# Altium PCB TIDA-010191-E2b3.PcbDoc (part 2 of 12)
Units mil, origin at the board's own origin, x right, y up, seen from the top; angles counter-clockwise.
Board outline 9842.52 x 9842.4 mil, 6 copper layers (Layer 1 - Top Layer, Layer 2 - GND Layer, Layer 3 - Signal, Layer 4 - Signal, Layer 5 - GND, Bottom Layer), stack 59.9 mil thick; 1178 components, 642 nets, 3329 pads, 2967 vias.
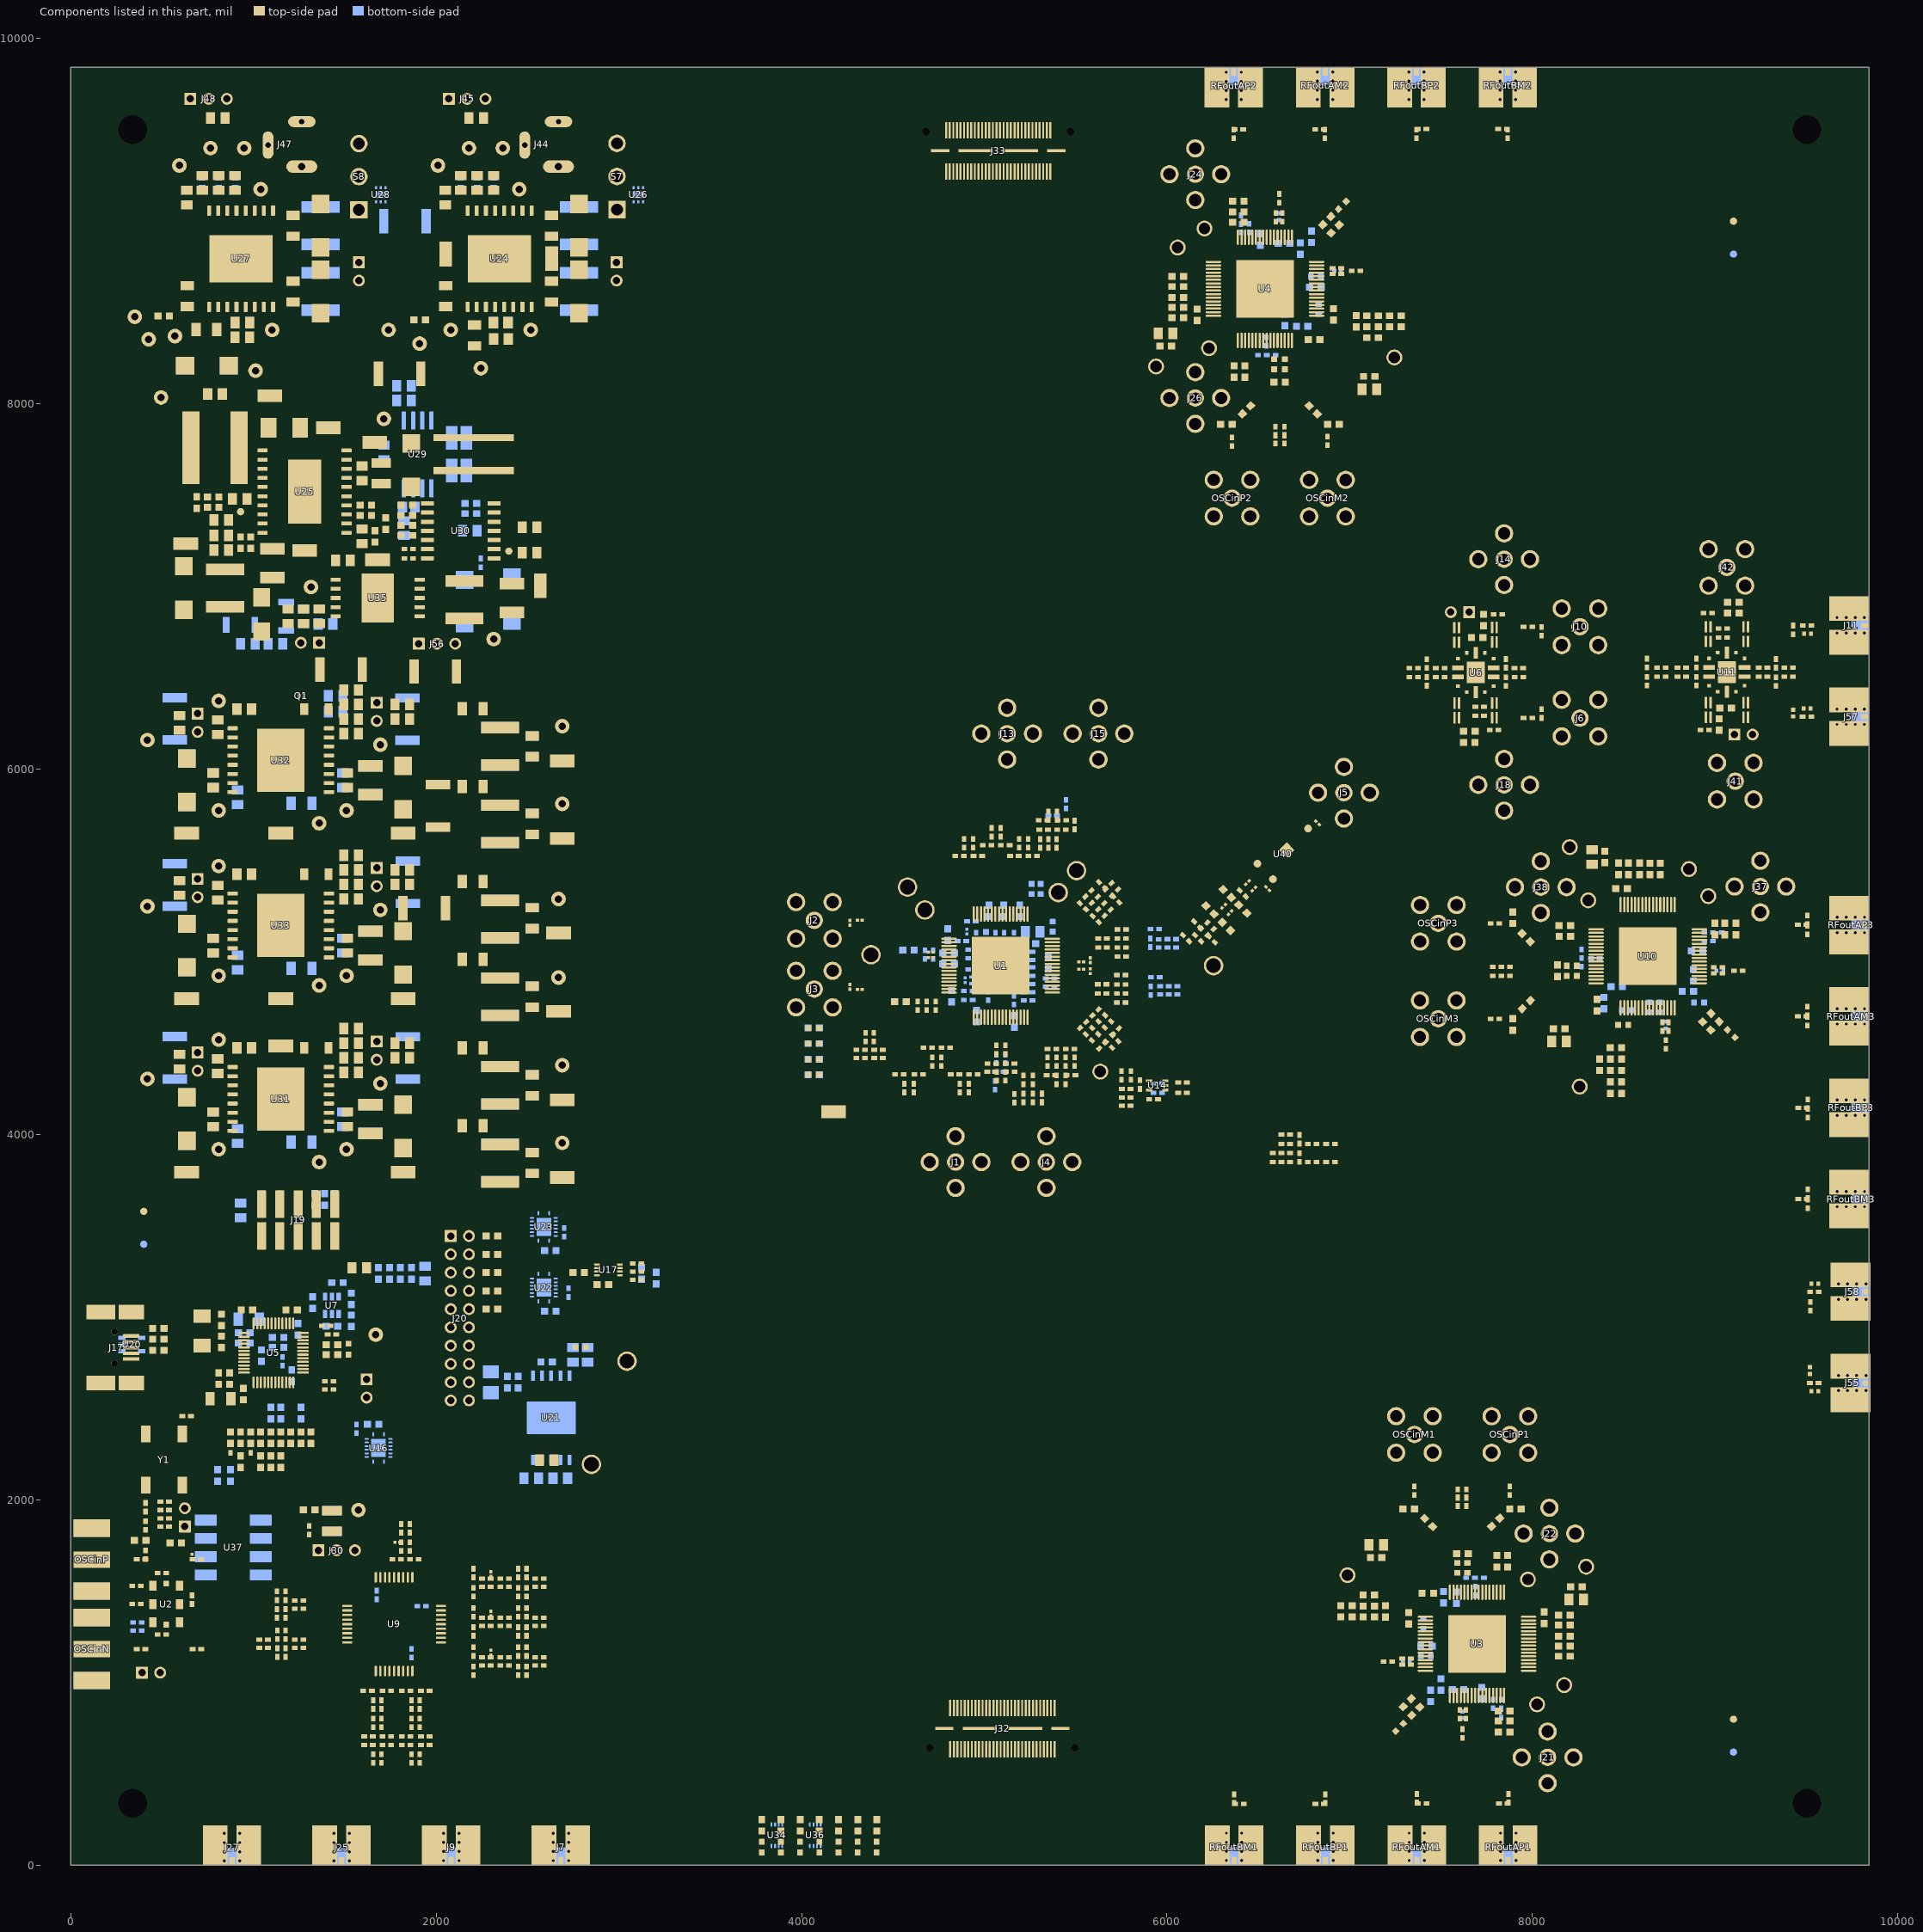
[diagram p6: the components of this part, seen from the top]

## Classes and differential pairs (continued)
net class C230_Nets: GND P3V8
net class C229_Nets: NetC229_1 VSENSE
net class C228_Nets: GND VIN_P5V0
net class C227_Nets: GND VIN_P5V0
net class C226_Nets: GND NetC226_2
net class C225_Nets: NetC223_1 P5V0
net class C224_Nets: NetC223_1 P5V0
net class C223_Nets: NetC223_1 VIN_P5V0
net class C222_Nets: GND VREGIN
net class C221_Nets: GND VREGIN
net class C220_Nets: GND VREGIN
net class C219_Nets: GND VREGIN
net class C218_Nets: GND VREGIN
net class C217_Nets: NetC217_1 NetC217_2
net class C213_Nets: GND NetC213_1
net class C212_Nets: GND NetC212_1
net class C211_Nets: GND NetC210_1
net class C210_Nets: GND NetC210_1
net class C209_Nets: GND NetC208_2
net class C208_Nets: GND NetC208_2
net class C207_Nets: NetC206_1 NetC207_2
net class C206_Nets: GND NetC206_1
net class C205_Nets: GND NetC203_1
net class C204_Nets: LMX3_RFoutA3_N NetC204_1
net class C203_Nets: NetC203_1 NetC203_2
net class C202_Nets: LMX3_RFoutA3_P NetC202_1
net class C201_Nets: GND P4V5
net class C200_Nets: GND P4V5
net class C199_Nets: GND VREGIN
net class C198_Nets: GND P4V5
net class C197_Nets: GND P4V5
net class C196_Nets: GND VREGIN
net class C195_Nets: LMX2_OSCin- NetC195_1
net class C194_Nets: LMX_OSCin3- NetC194_1
net class C193_Nets: LMX_OSCin3+ NetC193_1
net class C192_Nets: ADC_SYSREF2- RFoutB2_P
net class C191_Nets: LMX2_OSCin+ NetC191_1
net class C190_Nets: GND NetC190_1
net class C189_Nets: GND NetC189_2
net class C188_Nets: GND NetC187_2
net class C187_Nets: GND NetC187_2
net class C186_Nets: CPout1 GND
net class C185_Nets: GND SYNC
net class C184_Nets: GND RESET
net class C183_Nets: GND NetC183_1
net class C182_Nets: GND NetC182_1
net class C181_Nets: ADC_SYSREF3- RFoutB3_P
net class C180_Nets: GND NetC180_1
net class C175_Nets: GND NetC172_1
net class C174_Nets: GND NetC174_1
net class C173_Nets: GND NetC173_2
net class C172_Nets: NetC172_1 NetC172_2
net class C171_Nets: GND NetC171_1
net class C170_Nets: GND NetC170_2
net class C169_Nets: GND NetC169_2
net class C168_Nets: GND NetC168_1
net class C167_Nets: GND NetC167_2
net class C166_Nets: ADC_SYSREF3+ RFoutB3_N
net class C165_Nets: GND NetC165_2
net class C164_Nets: GND NetC164_2
net class C163_Nets: GND P3V3_LMX
net class C162_Nets: GND P3V3_LMX
net class C161_Nets: GND P3V3_LMX
net class C160_Nets: GND P3V3_LMX
net class C159_Nets: GND NetC159_1
net class C158_Nets: ADC_CLK3- RFoutA3_N
net class C157_Nets: GND NetC157_2
net class C156_Nets: GND NetC156_2
net class C155_Nets: GND NetC155_2
net class C154_Nets: GND NetC154_2
net class C153_Nets: ADC_CLK3+ RFoutA3_P
net class C152_Nets: GND NetC152_1
net class C151_Nets: GND NetC151_1
net class C150_Nets: GND NetC150_2
net class C149_Nets: GND NetC149_1
net class C148_Nets: GND NetC146_1
net class C147_Nets: GND NetC147_1
net class C146_Nets: NetC146_1 NetC146_2
net class C145_Nets: GND NetC145_2
net class C144_Nets: GND NetC144_1
net class C143_Nets: GND NetC143_2
net class C142_Nets: ADC_SYSREF2+ RFoutB2_N
net class C141_Nets: ADC_CLK2- RFoutA2_N
net class C140_Nets: GND NetC140_2
net class C139_Nets: GND NetC139_2
net class C138_Nets: GND NetC138_2
net class C137_Nets: NetC137_1 NetC137_2
net class C136_Nets: NetC136_1 NetC136_2
net class C135_Nets: NetC135_1 NetC135_2
net class C134_Nets: LMX3_RFoutB3_N NetC134_1
net class C133_Nets: NetC105_2 NetC133_2
net class C132_Nets: NetC132_1 NetC132_2
net class C131_Nets: GND NetC131_2
net class C130_Nets: GND NetC130_2
net class C129_Nets: GND NetC129_2
net class C128_Nets: GND NetC128_2
net class C127_Nets: GND P3V3_LMX
net class C126_Nets: GND OSCO
net class C125_Nets: GND OSCI
net class C124_Nets: GND VREGIN
net class C123_Nets: GND P3V3_LMX
net class C122_Nets: GND P3V3_LMX
net class C121_Nets: GND P3V3_LMX
net class C118_Nets: ADC_CLK2+ RFoutA2_P
net class C117_Nets: GND VREGIN
net class R174_Nets: GND USB_RESET
net class C115_Nets: GND VCCA
net class C114_Nets: GND VPLL
net class C113_Nets: GND NetC113_2
net class C112_Nets: GND VPLL
net class C111_Nets: GND VPHY
net class C110_Nets: GND VREGIN
net class C109_Nets: GND VREGIN
net class C108_Nets: GND VREGIN
net class C107_Nets: GND VPHY
net class C106_Nets: GND VREGIN
net class C105_Nets: NetC105_1 NetC105_2
net class C104_Nets: GND NetC104_1
net class C103_Nets: GND NetC103_1
net class C102_Nets: GND NetC102_1
net class C101_Nets: GND NetC101_1
net class C100_Nets: GND NetC100_2
net class C99_Nets: GND NetC99_1
net class C98_Nets: GND NetC98_2
net class C97_Nets: C_VCC GND
net class C96_Nets: C_VCC GND
net class C95_Nets: C_VCC GND
net class C94_Nets: C_VCC GND
net class C93_Nets: C_VCC GND
net class C92_Nets: NetC92_1 NetC92_2
net class C89_Nets: LMK6_OUT_N NetC89_2
net class C88_Nets: LMK6_OUT_P NetC88_2
net class C87_Nets: LMK_VCXO NetC87_1
net class C86_Nets: NetC86_1 NetC86_2
net class C85_Nets: GND Vcc10_PLL2
net class C84_Nets: GND NetC19_2
net class C83_Nets: GND NetC19_2
net class C80_Nets: CLKin1c_N CLKin1d_N
net class C79_Nets: CLKin1c_P CLKin1d_P
net class C78_Nets: GND NetC78_1
net class C77_Nets: GND NetC77_1
net class C76_Nets: GND NetC75_1
net class C75_Nets: GND NetC75_1
net class C74_Nets: GND NetC73_2
net class C73_Nets: GND NetC73_2
net class C72_Nets: LMX1_OSCin- NetC72_1
net class C71_Nets: LMX1_OSCin+ NetC71_1
net class C70_Nets: NetC68_1 NetC70_2
net class C69_Nets: NetC69_1 NetC69_2
net class C68_Nets: GND NetC68_1
net class C67_Nets: GND NetC66_1
net class C66_Nets: NetC66_1 NetC66_2
net class C65_Nets: NetC65_1 NetC65_2
net class C64_Nets: ADC_SYSREF1- RFoutB1_P
net class C63_Nets: GND P4V5
net class C62_Nets: GND NetC60_1
net class C61_Nets: GND NetC61_1
net class C60_Nets: NetC60_1 NetC60_2
net class C59_Nets: GND NetC59_1
net class C58_Nets: GND NetC58_2
net class C57_Nets: ADC_SYSREF1+ RFoutB1_N
net class C56_Nets: GND NetC56_2
net class C55_Nets: GND NetC55_2
net class C54_Nets: GND P3V3_LMX
net class C53_Nets: GND P3V3_LMX
net class C52_Nets: GND P3V3_LMX
net class C51_Nets: GND P3V3_LMX
net class C50_Nets: GND NetC50_2
net class C49_Nets: GND NetC49_2
net class C48_Nets: ADC_CLK1- RFoutA1_N
net class C47_Nets: GND NetC47_2
net class C46_Nets: GND NetC46_2
net class C45_Nets: GND NetC45_1
net class C44_Nets: ADC_CLK1+ RFoutA1_P
net class C43_Nets: GND P4V5
net class C42_Nets: GND P4V5
net class C41_Nets: GND P4V5
net class C40_Nets: CLKin1c_N GND
net class C39_Nets: CLKin1c_N NetC39_1
net class C38_Nets: CLKin1c_P NetC38_1
net class C37_Nets: CLKin0_N CLKINN1
net class C36_Nets: CLKin0_P CLKINP1
net class C35_Nets: GND Vcc12_CG0
net class C34_Nets: GND Vcc11_CG3
net class C33_Nets: GND Vcc4_CG2
net class C32_Nets: GND Vcc3_SYSREF
net class C31_Nets: GND Vcc9_CP2
net class C30_Nets: GND Vcc10_PLL2
net class C29_Nets: GND Vcc10_PLL2
net class C28_Nets: GND Vcc10_PLL2
net class C27_Nets: GND Vcc2_CG1
net class C26_Nets: GND Vcc8_OSCIN
net class C25_Nets: GND Vcc1_VCO
net class C24_Nets: GND Vcc1_VCO
net class C23_Nets: GND Vcc1_VCO
net class C22_Nets: GND NetC19_2
net class C21_Nets: GND LMK_LMX_DATA
net class C20_Nets: GND LMK_LMX_CLK
net class C19_Nets: GND NetC19_2
net class C18_Nets: GND LMK04832-SP_CSb
net class C17_Nets: CPout1 NetC17_2
net class C16_Nets: DCLKout2- DCLKout2_N
net class C15_Nets: DCLKout2+ DCLKout2_P
net class C14_Nets: GND NetC14_1
net class C13_Nets: GND NetC13_2
net class C12_Nets: LMK_VCXO OSCin+
net class C11_Nets: GND Vcc6_PLL1
net class C10_Nets: GND Vcc5_DIG
net class C9_Nets: NetC9_1 OSCin-
net class C8_Nets: CPout2 NetC8_1
net class C7_Nets: CPout2 GND
net class C6_Nets: DCLKout0- DCLKout0_N
net class C5_Nets: DCLKout0+ DCLKout0_P
net class C4_Nets: DCLKout12- DCLKout12_N DCLKout12a_N
net class C3_Nets: DCLKout12+ DCLKout12_P DCLKout12a_P
net class C2_Nets: GND VDDD33
net class C1_Nets: GND Vcc7_OSCOUT
differential pair class 100ohm: C1 C2 C3 C4 DCLKout0 DCLKout0* DCLKout0_LMK DCLKout2 DCLKout2* DCLKout2_LMK DCLKout12 DCLKOUT12 DCLKout12* DCLKout12_LMK DCLKout12a F_CORECLK1 F_CORECLK2 F_REFCLK1 F_REFCLK2 F_SYSREF1 F_SYSREF2 J1J4 J15J13 LMK_OSCin LMX3_RFoutA3 LMX3_RFoutB3 LMX2615-SP_1_REF LMX2615-SP_2_REF LMX2615-SP_3_REF newSDCLKout3 OSCin1 OSCin2 RFoutA1 RFoutA2 RFoutA3 RFoutB1 RFoutB2 RFoutB3 SDCLKout1 SDCLKout1_LMK SDCLKout3 SDCLKout3_LMK SDCLKout5* SDCLKout11 SDCLKout11a SDCLKOUT13 SDCLKout13 SDCLKout13_LMK SDCLKout13a SDCLKout13b
component class TIDA-010191-E2_Power-Supply_2: C135 C136 C137 C267 C268 C269 C270 C271 C272 C273 C274 C275 C276 C277 C278 C279 C280 C281 C282 C283 C284 C285 C286 C287 C288 C289 C290 C291 C292 C293 C294 C295 C296 C297 C298 C299 C300 C301 C302 C303 C304 C305 C306 C307 C308 C309 C310 C311 C312 C313 C314 C315 C326 C334 C339 C340 C341 C342 C343 C344 C345 C346 C347 C348 C349 C350 C351 C352 C353 C354 D14 D15 D16 D17 D18 D19 D20 D21 D22 J49 J50 J51 J52 J53 J54 J56 J59 L24 L25 L26 L27 L28 L29 R502 R503 R504 R505 R506 R507 R508 R509 R510 R511 R512 R513 R514 R515 R516 R517 R518 R519 R520 R521 R522 R523 R524 R525 R526 R527 R528 R529 R530 R531 R532 R533 R534 R535 R536 R537 R538 R539 R540 R541 R542 R543 R544 R545 R546 R547 R548 R549 R550 R551 R552 TP39 TP40 TP41 TP42 TP43 TP44 TP45 TP46 TP47 TP48 TP49 TP50 TP51 TP52 TP53 TP54 TP55 TP56 TP57 TP58 TP59 TP60 TP61 TP62 TP63 TP64 TP65 TP66 TP67 TP68 TP69 TP70 TP71 TP72 TP73 TP74 TP75 TP76 TP77 TP78 TP79 TP80 TP81 TP82 U31 U32 U33 U34 U35 U36
component class TIDA-010191-E2_Power-Supply_1: C223 C224 C225 C226 C227 C228 C229 C230 C231 C232 C233 C234 C235 C236 C237 C238 C239 C240 C241 C242 C243 C244 C245 C246 C247 C248 C249 C250 C251 C252 C253 C254 C255 C256 C257 C258 C259 C260 C261 C262 C263 C264 C265 C266 D12 J43 J44 J45 J46 J47 J48 L23 R407 R408 R409 R410 R411 R412 R413 R414 R415 R416 R417 R418 R419 R420 R421 R422 R423 R424 R425 R426 R427 R479 R480 R485 R486 R487 R488 R489 R490 R491 R492 R493 R494 R495 R496 R497 R498 R499 R500 R501 S7 S8 SH-J3 SH-J4 TP11 TP12 TP13 TP14 TP15 TP16 TP17 TP18 TP19 TP20 TP21 TP22 TP23 TP24 TP25 TP26 TP27 TP28 TP29 TP30 TP31 TP32 TP33 TP34 TP35 TP36 TP37 TP38 U24 U25 U26 U27 U28 U29 U30
component class TIDA-010191-E2_LMX2615_LO: C105 C133 C134 C153 C154 C155 C156 C157 C158 C159 C160 C161 C162 C163 C164 C165 C166 C167 C168 C169 C170 C171 C172 C173 C174 C175 C180 C181 C182 C183 C193 C194 C197 C198 C200 C201 C202 C203 C204 C205 C206 C207 C208 C209 C210 C211 C212 C213 C331 C332 C333 CE_TP3 D13 J11 J37 J38 J40 J41 J42 J55 J57 J58 L14 L21 L22 L32 L37 L38 L39 L40 OSCinM3 OSCinP3 R223 R224 R226 R227 R228 R229 R230 R231 R232 R250 R259 R261 R262 R263 R264 R265 R266 R267 R268 R269 R271 R272 R273 R277 R278 R279 R280 R281 R294 R295 R300 R301 R316 R317 R318 R319 R323 R324 R326 R328 R329 R330 R372 R373 R374 R375 R376 R377 R378 R379 R380 R478 R481 R482 R483 R484 RFoutAM3 RFoutAP3 RFoutBM3 RFoutBP3 RMPCLK3 RMPDIR3 SH-J2 U10 U11 Vcc_TP3 Vtune_TP3
component class TIDA-010191-E2_CDCLVP111: C9 C12 C88 C89 C92 C93 C94 C95 C96 C97 C132 C187 C188 C316 C317 C318 C319 C320 C321 C322 C323 C324 C325 J7 J9 J16 J25 J27 J30 L17 OSCinN OSCinP R34 R36 R37 R38 R39 R40 R43 R44 R45 R46 R51 R175 R177 R179 R180 R198 R199 R210 R220 R270 R299 R361 R362 R363 R364 R395 R396 R397 R398 R399 R400 R401 R402 R403 R404 R428 R429 R430 R431 R432 R433 R434 R435 R436 R437 R438 R439 R440 R441 R442 R443 R444 R445 R446 R447 R448 R449 R450 R451 R452 R453 R454 R455 R456 R457 R458 R459 R460 R461 R462 R463 R464 R465 R466 R467 R468 R469 R470 R471 R472 R473 R474 R475 R476 R477 SH-J30 TP8 U2 U9 U37
component class Shunt: SH-J1 SH-J2 SH-J3 SH-J4 SH-J30
component class TIDA-010191-E2_LMK04832: C1 C2 C3 C4 C5 C6 C7 C8 C10 C11 C13 C14 C15 C16 C17 C18 C19 C20 C21 C22 C23 C24 C25 C26 C27 C28 C29 C30 C31 C32 C33 C34 C35 C36 C37 C38 C39 C40 C41 C42 C43 C63 C65 C66 C67 C68 C69 C70 C73 C74 C75 C76 C77 C78 C79 C80 C83 C84 C85 C86 C87 C184 C185 C186 C355 C356 D1 D2 D3 D4 J1 J2 J3 J4 J5 J6 J8 J10 J12 J13 J14 J15 J18 L1 L2 L3 L4 L5 L6 L7 L8 L9 L10 L13 L30 L31 R1 R2 R3 R4 R5 R6 R7 R8 R9 R10 R11 R12 R13 R14 R15 R16 R17 R18 R19 R20 R21 R22 R23 R24 R25 R26 R27 R28 R29 R30 R31 R32 R33 R35 R41 R42 R47 R48 R49 R50 R52 R53 R54 R55 R56 R57 R58 R59 R60 R61 R62 R63 R64 R65 R66 R67 R68 R69 R70 R71 R72 R73 R74 R75 R76 R77 R78 R79 R80 R81 R84 R92 R98 R99 R100 R101 R103 R106 R108 R110 R111 R114 R115 R116 R117 R118 R119 R120 R121 R122 R123 R124 R125 R126 R127 R128 R129 R130 R131 R132 R133 R134 R135 R136 R137 R138 R139 R140 R141 R142 R143 R144 R145 R146 R148 R164 R165 R166 R167 R168 R169 R170 R171 R182 R183 R184 R190 R191 R192 R193 R194 R195 R196 R197 R200 R201 R202 R203 R204 R208 R209 R215 R216 R233 R282 R283 R284 R285 R286 R287 R288 R289 R290 R291 R292 R293 R297 R298 R335 R336 R337 R338 R339 R343 R344 R345 R346 R356 R357 R366 R391 R392 R393 R394 R553 R554 R555 R556 SH-J1 SYNC TP1 TP2 TP3 TP4 TP5 TP83 TP84 U1 U6 U14 U40 Y1
component class Header: J8 J12 J16 J20 J30 J39 J40 J43 J45 J46 J48 J49 J50 J51 J52 J53 J54 J56 J59
component class Label: LBL1
component class AssemblyNote: ZZ1 ZZ2 ZZ3 ZZ4
component class FiducialMark: FID1 FID2 FID3 FID4 FID5 FID6
component class TIDA-010191-E2_Hardware: FID1 FID2 FID3 FID4 FID5 FID6 LBL1 Logo1 Logo2 Logo3 Logo4 s1 S1 S2 S3 S4 ZZ1 ZZ2 ZZ3 ZZ4
component class TIDA-010191-E2_LMX2615: C44 C45 C46 C47 C48 C49 C50 C51 C52 C53 C54 C55 C56 C57 C58 C59 C60 C61 C62 C64 C71 C72 C98 C99 C100 C101 C102 C103 C104 C118 C121 C122 C123 C127 C128 C129 C130 C131 C138 C139 C140 C141 C142 C143 C144 C145 C146 C147 C148 C149 C150 C151 C152 C189 C190 C191 C192 C195 CE_TP1 CE_TP2 D5 D6 J21 J22 J24 J26 L11 L12 L18 L19 OSCinM1 OSCinM2 OSCinP1 OSCinP2 R82 R83 R85 R86 R87 R88 R89 R90 R91 R93 R94 R95 R96 R97 R102 R104 R105 R107 R109 R112 R113 R213 R214 R234 R235 R236 R237 R238 R239 R240 R241 R242 R243 R244 R245 R246 R247 R248 R249 R251 R252 R253 R254 R255 R256 R257 R258 R260 R274 R275 R276 R313 R314 R315 R320 R321 R322 R325 R327 R331 R332 R333 R334 R342 R347 R348 R349 R350 R351 R352 R353 R354 R355 R358 R359 R360 RFoutAM1 RFoutAM2 RFoutAP1 RFoutAP2 RFoutBM1 RFoutBM2 RFoutBP1 RFoutBP2 RMPCLK1 RMPCLK2 RMPDIR1 RMPDIR2 U3 U4 Vcc_TP1 Vcc_TP2 Vtune_TP1 Vtune_TP2
component class TIDA-010191-E2_USB: C106 C107 C108 C109 C110 C111 C112 C113 C114 C115 C117 C124 C125 C126 C196 C199 C217 C218 C219 C220 C221 C222 C327 C328 C329 C335 C337 D7 D10 J17 J19 J20 J32 J33 J39 L15 L16 NT1 NT2 Q1 R147 R149 R150 R151 R152 R153 R154 R155 R156 R157 R158 R159 R160 R161 R162 R163 R172 R173 R174 R178 R181 R185 R186 R187 R188 R189 R205 R206 R207 R211 R212 R217 R218 R219 R225 R296 R302 R303 R304 R305 R306 R307 R308 R309 R310 R311 R312 R340 R341 R370 R371 R381 R383 R384 R385 R386 R387 R388 R389 R390 R405 R557 R558 R559 R560 TP9 TP10 U5 U7 U16 U17 U20 U21 U22 U23 VCCCORE Y2
differential pair SDCLKout3: +SDCLKout3_P -SDCLKout3_N
differential pair SDCLKout13: +SDCLKOUT13_P -SDCLKOUT13_N
differential pair SDCLKout1: +SDCLKOUT1_P -SDCLKOUT1_N
differential pair DCLKout12: +DCLKOUT12_P -DCLKOUT12_N
differential pair DCLKout2: +DCLKOUT2_P -DCLKOUT2_N
differential pair DCLKout0: +DCLKOUT0_P -DCLKOUT0_N
differential pair C4: +C4_P -C4_N
differential pair C3: +C3_P -C3_N
differential pair C2: +C2_P -C2_N
differential pair C1: +C1_P -C1_N
differential pair LMX2615-SP_3_REF: +LMX2615-SP_3_REF_P -LMX2615-SP_3_REF_N
differential pair SDCLKout11: +SDCLKout11_P -SDCLKout11_N
differential pair SDCLKout11a: +SDCLKout11a_P -SDCLKout11a_N
differential pair LMK6_OUT: +LMK6_OUT_P -LMK6_OUT_N
differential pair SDCLKout13b: +SDCLKout13b_P -SDCLKout13b_N
differential pair SDCLKout13a: +SDCLKout13a_P -SDCLKout13a_N
differential pair DCLKout12a: +DCLKout12a_P -DCLKout12a_N
differential pair CLKin1d: +CLKin1d_P -CLKin1d_N
differential pair CLKin1c: +CLKin1c_P -CLKin1c_N
differential pair SDCLKout5*: +SDCLKout5*_P -SDCLKout5*_N
differential pair OSCin2: +OSCin2_P -OSCin2_N
differential pair OSCin1: +OSCin1_P -OSCin1_N
differential pair LMX2615-SP_2_REF: +LMX2615-SP_2_REF_P -LMX2615-SP_2_REF_N
differential pair LMX2615-SP_1_REF: +LMX2615-SP_1_REF_P -LMX2615-SP_1_REF_N
differential pair J15J13: +J15J13_P -J15J13_N
differential pair J1J4: +J1J4_P -J1J4_N
differential pair LMX3_RFoutB3: +LMX3_RFoutB3_P -LMX3_RFoutB3_N
differential pair LMX3_RFoutA3: +LMX3_RFoutA3_P -LMX3_RFoutA3_N
differential pair RFoutB3: +RFoutB3_P -RFoutB3_N
differential pair RFoutB2: +RFoutB2_P -RFoutB2_N
differential pair RFoutB1: +RFoutB1_P -RFoutB1_N
differential pair RFoutA3: +RFoutA3_P -RFoutA3_N
differential pair RFoutA2: +RFoutA2_P -RFoutA2_N
differential pair RFoutA1: +RFoutA1_P -RFoutA1_N
differential pair DCLKout12*: +DCLKout12*_P -DCLKout12*_N
differential pair DCLKout2*: +DCLKout2*_P -DCLKout2*_N
differential pair DCLKout0*: +DCLKout0*_P -DCLKout0*_N
differential pair SDCLKout3_LMK: +SDCLKout3_LMK_P -SDCLKout3_LMK_N
differential pair SDCLKout1_LMK: +SDCLKout1_LMK_P -SDCLKout1_LMK_N
differential pair CDCLVP_CLK1: +CDCLVP_CLK1_P -CDCLVP_CLK1_N
differential pair USB: +USB_P -USB_N
differential pair D: +D_P -D_N
differential pair CDCM7005-SP_VCXO_IN: +CDCM7005-SP_VCXO_IN_P -CDCM7005-SP_VCXO_IN_N
differential pair SDCLKout13_LMK: +SDCLKout13_LMK_P -SDCLKout13_LMK_N
differential pair DCLKout12_LMK: +DCLKout12_LMK_P -DCLKout12_LMK_N
differential pair LMK_OSCin: +LMK_OSCin_P -LMK_OSCin_N
differential pair DCLKout2_LMK: +DCLKout2_LMK_P -DCLKout2_LMK_N
differential pair DCLKout0_LMK: +DCLKout0_LMK_P -DCLKout0_LMK_N
differential pair F_CORECLK1: +F_CORECLK1_P -F_CORECLK1_N
differential pair CLKIN0: +CLKIN0_P -CLKIN0_N
differential pair CLKIN1: +CLKIN1_P -CLKin1_N
differential pair F_CORECLK2: +F_CORECLK2_P -F_CORECLK2_N
differential pair F_REFCLK1: +F_REFCLK1_P -F_REFCLK1_N
differential pair F_REFCLK2: +F_REFCLK2_P -F_REFCLK2_N
differential pair F_SYSREF1: +F_SYSREF1_P -F_SYSREF1_N
differential pair F_SYSREF2: +F_SYSREF2_P -F_SYSREF2_N
differential pair OSCOUT: +OSCout_P -OSCout_N

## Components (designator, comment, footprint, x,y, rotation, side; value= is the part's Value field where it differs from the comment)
C1 "Capacitor" 0402 4935,4964.37 r0 bottom value=0.1uF
C2 "Capacitor" 0402 5926.89,4194.09 r0 top value=0.1uF
C3 "Capacitor" 0402 5395,4400 r270 top value=0.1uF
C4 "Capacitor" 0402 5445,4400 r270 top value=0.1uF
C5 "Capacitor" 0402 5607,4567 r315 top value=0.1uF
C6 "Capacitor" 0402 5642,4603 r315 top value=0.1uF
C7 "Capacitor" 0201_033 4940,4862.92 r0 bottom value=47pF
C8 "Capacitor" 0201 4894.36,4845.27 r90 bottom value=3900pF
C9 "Capacitor" 0402 691.36,1183.92 r0 top value=0.1uF
C10 "Capacitor" 0402 4935,5011.5 r0 bottom value=1uF
C11 "Capacitor" 0402 4720,4985 r270 bottom value=1uF
C12 "Capacitor" 0402 691.36,1674.93 r0 top value=0.1uF
C13 "CMP-0007732-2" 0805_HV 5265,5110 r0 bottom value=10uF
C14 "Capacitor" 0603 5250,5045 r180 bottom value=0.1uF
C15 "Capacitor" 0402 5640,5250 r45 top value=0.1uF
C16 "Capacitor" 0402 5605,5285 r45 top value=0.1uF
C17 "Capacitor" 0402 4929.7,5168.58 r180 bottom value=0.68uF
C18 "Capacitor" 0603L 5307.5,5345 r270 bottom value=33pF
C19 "Capacitor" 0402 515,1855 r0 top value=0.1uF
C20 "Capacitor" 0603L 5259.68,5345 r270 bottom value=33pF
C21 "Capacitor" 0603L 5373.57,5139.33 r90 bottom value=33pF
C22 "CMP-0006196-2" 0402 515,1900 r0 top value=100pF
C23 "Capacitor" 0402 5240,4915 r180 bottom value=1uF
C24 "Capacitor" 0402 5240,4955 r180 bottom value=0.1uF
C25 "Capacitor" 0402 5240,5000 r180 bottom value=0.01uF
C26 "Capacitor" 0402 4935,4905 r180 bottom value=0.1uF
C27 "Capacitor" 0402 5162.02,5081.38 r270 bottom value=1uF
C28 "Capacitor" 0402 4635,4705 r270 top value=1uF
C29 "Capacitor" 0402 4685,4705 r270 top value=0.1uF
C30 "Capacitor" 0402 4735,4705 r270 top value=0.01uF
C31 "Capacitor" 0402 4912.44,4786.5 r180 bottom value=0.1uF
C32 "Capacitor" 0402 5108.52,5081.38 r270 bottom value=1uF
C33 "Capacitor" 0402 5061.06,5081.38 r270 bottom value=1uF
C34 "Capacitor" 0402 5022,4760 r90 bottom value=1uF
C35 "Capacitor" 0402 5163.5,4736.38 r90 bottom value=1uF
C36 "Capacitor" 0201_033 4706.89,4999.09 r0 top value=0.1uF
C37 "Capacitor" 0201_033 4706.89,4969.09 r0 top value=0.1uF
C38 "Capacitor" 0402 6238.74,5108.7 r225 top value=0.1uF
C39 "Capacitor" 0402 6203.74,5143.7 r225 top value=0.1uF
C40 "CMP-0006295-2" 0402 6104.26,5075 r315 top value=0.1uF
C41 "CMP-0009493-2" 0306 7585,6695 r180 top value=2200pF
C42 "Capacitor" 0306 7585,6775 r0 top value=0.01uF
C43 "CMP-0009493-2" 0306 7586.31,6362.18 r180 top value=2200pF
C44 "Capacitor" 0402_065 7868.19,367.31 r90 top value=0.01uF
C45 "Capacitor" 0402_065 7616,722 r270 top value=0.01uF
C46 "CMP-0007037-4" 0603 8175,1315 r180 top value=1uF
C47 "CMP-0007037-4" 0603 7845,790 r180 top value=1uF
C48 "Capacitor" 0402_065 7368.19,367.31 r90 top value=0.01uF
C49 "CMP-0007037-4" 0603 7420,1200 r180 bottom value=1uF
C50 "CMP-0006808-4" 0603 7442.35,927.98 r90 bottom value=0.1uF
C51 "Capacitor" 0603 8240,1525 r0 top value=0.1uF
C52 "CMP-0007732-2" 0805_HV 8240,1455 r0 top value=10uF
C53 "CMP-0007732-2" 0805_HV 7145,1755 r0 top value=10uF
C54 "Capacitor" 0603 7145,1685 r0 top value=0.1uF
C55 "CMP-0007037-4" 0603 7322.35,1352.49 r270 top value=1uF
C56 "CMP-0007037-4" 0603 7585,1465 r270 bottom value=1uF
C57 "Capacitor" 0402_065 6367.17,364.85 r90 top value=0.01uF
C58 "Capacitor" 0603 8175,1200 r180 top value=1800pF
C59 "CMP-0007262-4" 0603 6982.45,1420.54 r180 top value=300pF
C60 "Capacitor" 0603 7105,1360 r180 top value=0.056uF
C61 "Capacitor" 0402_065 7209.2,1116.31 r180 top value=0.01uF
C62 "Capacitor" 0603 7195,1390 r90 top value=1500pF
C63 "Capacitor" 0306 7586.31,6282.18 r180 top value=0.01uF
C64 "Capacitor" 0402_065 6867.17,364.85 r90 top value=0.01uF
C65 "GRM155R6YA105KE11D" 0402 7975,6280 r0 top value=1uF
C66 "GRM155R6YA105KE11D" 0402 7495,6505 r0 top value=1uF
C67 "500R07S0R3BV4T" 0402 7421.38,6480.79 r270 top value=0.3pF
C68 "500R07S0R3BV4T" 0402 7421.38,6579.21 r90 top value=0.3pF
C69 "GRM155R6YA105KE11D" 0402 7975,6780 r0 top value=1uF
C70 "GRM155R6YA105KE11D" 0402 7495,6555 r0 top value=1uF
C71 "Capacitor" 0603L 7644.15,1628.51 r270 top value=0.1uF
C72 "Capacitor" 0603L 7588.97,1628.51 r270 top value=0.1uF
C73 "CMP-0009490-2" 0306 7791.31,6777.18 r180 top value=0.01uF
C74 "CMP-0009493-2" 0306 7791.31,6697.18 r0 top value=2200pF
C75 "CMP-0009493-2" 0306 7791.31,6362.18 r0 top value=2200pF
C76 "CMP-0009490-2" 0306 7791.31,6282.18 r180 top value=0.01uF
C77 "GRM155R6YA105KE11D" 0402 7711.31,6342.18 r0 top value=1uF
C78 "GRM188R71C103KA01D" 0603 7731.49,6816.65 r90 top value=0.01uF
C79 "Capacitor" 0402 6245,5070 r135 top value=0.1uF
C80 "Capacitor" 0402 6165,5150 r315 top value=0.1uF
C83 "Capacitor" 0402 515,1945 r0 top value=2200pF
C84 "Capacitor" 0402 515,1990 r0 top value=10pF
C85 "Capacitor" 0402 4912.5,4736.38 r180 bottom value=0.1uF
C86 "Capacitor" 0402 410,1960 r270 top value=0.1uF
C87 "Capacitor" 0402 410,1700 r270 top value=0.1uF
C88 "Capacitor" 0402 1056,1236 r0 top value=0.1uF
C89 "Capacitor" 0402 1056,1191 r0 top value=0.1uF
C92 "CMP-0006210-2" 0402_065 1700,780 r90 top value=0.01uF
C93 "GRM32ER61A226KE20L" 1210_270 1430,1885 r270 top value=22uF
C94 "C1210C106K8PACTU" 1210_210 1430,1885 r270 bottom value=10uF
C95 "885012105016" 0402 1675,1480 r270 bottom value=0.1uF
C96 "GRM155R61C333KA01D" 0402 1921.38,1420 r180 bottom value=0.033uF
C97 "GCM155R71E103KA37D" 0402 1865.15,1160.96 r90 bottom value=0.01uF
C98 "CMP-0007037-4" 0603 7427.45,1490.54 r0 top value=1uF
C99 "CMP-0007003-5" 0603 8175,1255 r0 top value=10uF
C100 "CMP-0007037-4" 0603 8065,1355 r270 top value=1uF
C101 "CMP-0007003-5" 0603 7845,845 r0 top value=10uF
C102 "CMP-0007003-5" 0603 7805,1665 r90 top value=10uF
C103 "CMP-0007003-5" 0603 7722.35,942.98 r270 bottom value=10uF
C104 "CMP-0007003-5" 0603 8175,1145 r0 top value=10uF
C105 "GRM155R6YA105KE11D" 0402 9502.65,6787.89 r180 top value=1uF
C106 "CMP-0007003-5" 0603 1135,2835 r180 bottom value=10uF
C107 "CMP-0007003-5" 0603 950,2915 r0 bottom value=10uF
C108 "Capacitor" 0603 945,2580 r270 top value=0.1uF
C109 "Capacitor" 0603 1210,2680.59 r90 bottom value=0.1uF
C110 "Capacitor" 0603 965,3040 r180 top value=0.1uF
C111 "Capacitor" 0603 950,2860 r0 bottom value=0.1uF
C112 "CMP-0007003-5" 0603 810,2665 r270 top value=10uF
C113 "Capacitor" 0603 1245,2935 r270 bottom value=0.1uF
C114 "Capacitor" 0603 870,2665 r270 top value=0.1uF
C115 "Capacitor" 0603 1210,3040 r0 top value=0.1uF
C117 "Capacitor" 0603 1135,2890 r180 bottom value=0.1uF
C118 "Capacitor" 0402_065 6364.12,9477.44 r270 top value=0.01uF
C121 "Capacitor" 0603 5992.61,8317.44 r180 top value=0.1uF
C122 "CMP-0007732-2" 0805_HV 5992.61,8385.63 r180 top value=10uF
C123 "CMP-0007732-2" 0805_HV 7106.86,8079.2 r180 top value=10uF
C124 "Capacitor" 0603 1535,3100.59 r90 bottom value=0.1uF
C125 "Capacitor" 0603 825,2985.59 r270 top value=27pF
C126 "Capacitor" 0603 825,2865.59 r270 top value=27pF
C127 "Capacitor" 0603 7107.18,8150.62 r180 top value=0.1uF
C128 "CMP-0007037-4" 0603 6058.61,8527.44 r0 top value=1uF
C129 "CMP-0007037-4" 0603 6645,8460 r270 bottom value=1uF
C130 "CMP-0007037-4" 0603 6910,8490 r90 top value=1uF
C131 "Capacitor" 0402_065 6614.96,9125.65 r270 top value=0.01uF
C132 "CMP-0006210-2" 0402_065 1655,780 r90 top value=0.01uF
C133 "GRM155R6YA105KE11D" 0402 9426,6763 r270 top value=1uF
C134 "GRM155R6YA105KE11D" 0402 9519.71,3059.95 r270 top value=1uF
C135 "CGJ4C2C0G1H471J060AA" 0805_HV 1535,4500 r180 top value=470pF
C136 "CGJ4C2C0G1H471J060AA" 0805_HV 1535,6355.47 r180 top value=470pF
C137 "CGJ4C2C0G1H471J060AA" 0805_HV 1535,5450 r180 top value=470pF
C138 "CMP-0007037-4" 0603 6811.54,8639.87 r0 bottom value=1uF
C139 "CMP-0007037-4" 0603 6390,9050 r0 top value=1uF
C140 "CMP-0006808-4" 0603 6790,8915 r270 bottom value=0.1uF
C141 "Capacitor" 0402_065 6864.17,9477.44 r270 top value=0.01uF
C142 "Capacitor" 0402_065 7864.91,9477.44 r270 top value=0.01uF
C143 "CMP-0007037-4" 0603 6804.91,8352.44 r180 top value=1uF
C144 "CMP-0007003-5" 0603 6058.61,8582.44 r180 top value=10uF
C145 "CMP-0007037-4" 0603 6165.61,8487.44 r90 top value=1uF
C146 "Capacitor" 0603 7124.91,8482.44 r0 top value=0.056uF
C147 "CMP-0007003-5" 0603 6390,8995 r180 top value=10uF
C148 "Capacitor" 0603 7034.91,8452.44 r270 top value=1500pF
C149 "CMP-0007262-4" 0603 7249.91,8422.44 r0 top value=300pF
C150 "Capacitor" 0603 6058.61,8642.44 r0 top value=1800pF
C151 "CMP-0007003-5" 0603 6427.07,8176.71 r270 top value=10uF
C152 "CMP-0007003-5" 0603 6510,8900 r90 bottom value=10uF
C153 "Capacitor" 0402_065 9476.17,5148.38 r180 top value=0.01uF
C154 "Capacitor" 0603L 8911.56,4722.55 r180 bottom value=0.1uF
C155 "Capacitor" 0603 8461,4810 r180 bottom value=1uF
C156 "Capacitor" 0402_065 9127,4898 r180 top value=0.01uF
C157 "Capacitor" 0603L 8496,4600 r0 top value=1uF
C158 "Capacitor" 0402_065 9476.17,4648.38 r180 top value=0.01uF
C159 "Capacitor" 0603L 8640.37,4697.07 r90 bottom value=1uF
C160 "Capacitor" 0603 8396,5520 r90 top value=0.1uF
C161 "CMP-0007732-2" 0805_HV 8326,5520 r90 top value=10uF
C162 "CMP-0007732-2" 0805_HV 8146,4510 r0 top value=10uF
C163 "Capacitor" 0603 8146,4580 r0 top value=0.1uF
C164 "Capacitor" 0603 9053.48,5125.2 r270 top value=1uF
C165 "Capacitor" 0603 8526,5455 r270 top value=1uF
C166 "Capacitor" 0402_065 9478.63,3647.36 r180 top value=0.01uF
C167 "CMP-0007037-4" 0603 8352.94,4708.63 r90 top value=1uF
C168 "CMP-0007003-5" 0603 8586,5455 r90 top value=10uF
C169 "CMP-0007037-4" 0603 8487.94,5346.94 r0 top value=1uF
C170 "Capacitor" 0603 8642.94,5453.94 r270 top value=1800pF
C171 "CMP-0007262-4" 0603 8426.6,4257.55 r270 top value=300pF
C172 "Capacitor" 0603 8486.6,4382.55 r270 top value=0.056uF
C173 "Capacitor" 0402_065 8729.71,4493.18 r90 top value=0.01uF
C174 "CMP-0007003-5" 0603 8998.48,5125.2 r90 top value=10uF
C175 "Capacitor" 0603 8456,4475 r180 top value=1500pF
C180 "CMP-0007003-5" 0603 8177.69,5085.48 r180 top value=10uF
C181 "Capacitor" 0402_065 9478.63,4147.36 r180 top value=0.01uF
C182 "CMP-0007003-5" 0603 8901,5005 r0 bottom value=10uF
C183 "CMP-0007003-5" 0603 8699.32,5453.94 r90 top value=10uF
C184 "Capacitor" 0402 5240,4780 r180 bottom value=0.1uF
C185 "Capacitor" 0402 5240,4825 r180 bottom value=0.1uF
C186 "Capacitor" 0402 4955,5081.38 r90 bottom value=0.1uF
C187 "Capacitor" 0402 365,1285 r0 bottom value=4.7uF
C188 "Capacitor" 0402 365,1330 r0 bottom value=0.01uF
C189 "Capacitor" 0402_065 7034.91,8727.44 r180 top value=0.01uF
C190 "CMP-0007003-5" 0603 6058.61,8698.82 r180 top value=10uF
C191 "Capacitor" 0603L 6585.3,8217.44 r90 top value=0.1uF
C192 "Capacitor" 0402_065 7365.19,9478.13 r270 top value=0.01uF
C193 "Capacitor" 0603L 8214.97,4924.35 r0 top value=0.1uF
C194 "Capacitor" 0603L 8214.97,4869.17 r0 top value=0.1uF
C195 "Capacitor" 0603L 6644.91,8217.44 r90 top value=0.1uF
C196 "C0603C104J3RACTU" 0603 1655,2415 r0 bottom value=0.1uF
C197 "Capacitor" 0306 9167.44,6700.09 r0 top value=0.01uF
C198 "Capacitor" 0306 9167.44,6780.09 r0 top value=2200pF
C199 "Capacitor" 0603 2912.92,3180 r0 top value=0.1uF
C200 "Capacitor" 0306 9167.44,6365.09 r180 top value=0.01uF
C201 "Capacitor" 0306 9167.44,6285.09 r0 top value=2200pF
C202 "GRM155R6YA105KE11D" 0402 8705.24,6556.75 r180 top value=1uF
C203 "GRM155R6YA105KE11D" 0402 9262,6556.75 r180 top value=1uF
C204 "GRM155R6YA105KE11D" 0402 8705.24,6506.75 r180 top value=1uF
C205 "500R07S0R3BV4T" 0402 9332.44,6580.09 r90 top value=0.3pF
C206 "500R07S0R3BV4T" 0402 9332.44,6480.09 r270 top value=0.3pF
C207 "GRM155R6YA105KE11D" 0402 9262,6506.75 r180 top value=1uF
C208 "CMP-0009490-2" 0306 8962.44,6365.09 r0 top value=0.01uF
C209 "CMP-0009493-2" 0306 8962.44,6285.09 r180 top value=2200pF
C210 "CMP-0009493-2" 0306 8962.44,6780.09 r180 top value=2200pF
C211 "CMP-0009490-2" 0306 8962.44,6700.09 r0 top value=0.01uF
C212 "GRM155R6YA105KE11D" 0402 9042.44,6720.09 r180 top value=1uF
C213 "GRM188R71C103KA01D" 0603 9022.44,6245.09 r270 top value=0.01uF
C217 "GCM1885C2A101JA16D" 0603 2605,2755 r0 bottom value=100pF
C218 "GCM1885C2A101JA16D" 0603 2390,2645 r270 bottom value=100pF
C219 "0603YD105KAT2A" 0603 2450,2645 r270 bottom value=1uF
C220 "293D106X0010B2TE3" 3528-21 2300,2645 r270 bottom value=10uF
C221 "C0603C104J3RACTU" 0603 2625,3032.56 r180 bottom value=0.1uF
C222 "C0603C104J3RACTU" 0603 2625,3365 r180 bottom value=0.1uF
C223 "C0805C102J5RACTU" 0805_HV 2355,8445 r0 bottom value=1000pF
C224 "08053C104JAZ2A" 0805_HV 2352.56,8445 r180 top value=0.1uF
C225 "SR0805X7R333K1NT95(F)#M123A" 0805_HV 2355,8355 r180 top value=0.033uF
C226 "SR0603X7R103K1NT95(F)#M123A" 0603 985,7240 r90 top value=0.01uF
C227 "T530X337M010ATE006" 7343-43 2782.56,8975 r270 top value=330uF
C228 "12065C104JAT2A" 1206 2632.56,8975 r90 top value=0.1uF
C229 "SR0805X7R681K3NT95(F)#M123A" 0805_HV 825,7365 r0 top value=680pF
C230 "T541X337M010AH6720" 7343-43 746,8210 r0 top value=330uF
C231 "T541X337M010AH6720" 7343-43 746,8210 r0 bottom value=330uF
C232 "SR0805X7R104K1NT95(F)#M123A" 0805_HV 790,8055 r0 top value=0.1uF
C233 "T541X337M010AH6720" 7343-43 1865,7665 r90 top value=330uF
C234 "22201C106MAT2A" 2220_280 2782.56,8975 r270 bottom value=10uF
C235 "C1210C475K8RACTU" 1210 1700,7620 r90 top value=4.7uF
C236 "08055C104JAT2A" 0805_HV 1595,7620 r90 top value=0.1uF
C237 "T530X337M010ATE006" 7343-43 2782.56,8615 r90 top value=330uF
C238 "12065C104JAT2A" 1206 2632.56,8615 r270 top value=0.1uF
C239 "C2012X7R1H474K125AB" 0805_HV 925,7480 r180 top value=0.47uF
C240 "22201C106MAT2A" 2220_280 2782.56,8615 r90 bottom value=10uF
C241 "08053C104JAZ2A" 0805_HV 2135,9210 r90 top value=0.1uF
C242 "08053C104JAZ2A" 0805_HV 2225,9210 r90 top value=0.1uF
C243 "08053C104JAZ2A" 0805_HV 2315,9210 r90 top value=0.1uF
C244 "08055C104JAT2A" 0805_HV 1595,7275 r270 top value=0.1uF
C245 "SR0805X7R681K3NT95(F)#M123A" 0805_HV 825,7280 r180 top value=680pF
C246 "12065A202JAT2A" 1206 2210,8375 r90 top value=2000pF
C247 "12065A202JAT2A" 1206 2052.56,8590 r270 top value=2000pF
C248 "SR0805X7R333K1NT95(F)#M123A" 0805_HV 825,7200 r180 top value=0.033uF
C249 "C0805C102J5RACTU" 0805_HV 940,8445 r0 bottom value=1000pF
C250 "08053C104JAZ2A" 0805_HV 940,8445 r180 top value=0.1uF
C251 "SR0805X7R333K1NT95(F)#M123A" 0805_HV 940,8365 r180 top value=0.033uF
C252 "T530X337M010ATE006" 7343-43 1367.56,8615 r90 top value=330uF
C253 "22201C106MAT2A" 2220_280 1367.56,8615 r90 bottom value=10uF
C254 "12065C104JAT2A" 1206 1217.56,8615 r270 top value=0.1uF
C255 "T530X337M010ATE006" 7343-43 1367.56,8975 r270 top value=330uF
C256 "12065C104JAT2A" 1206 1217.5,8975 r90 top value=0.1uF
C257 "22201C106MAT2A" 2220_280 1367.56,8975 r270 bottom value=10uF
C258 "08053C104JAZ2A" 0805_HV 720,9210 r90 top value=0.1uF
C259 "08053C104JAZ2A" 0805_HV 810,9210 r90 top value=0.1uF
C260 "08053C104JAZ2A" 0805_HV 900,9210 r90 top value=0.1uF
C261 "C0805C103F1GACTU" 0805_HV 1825,7320 r270 bottom value=0.01uF
C262 "12065A202JAT2A" 1206 743,8407 r0 top value=2000pF
C263 "12065A202JAT2A" 1206 637.56,8590 r270 top value=2000pF
C264 "C0805C103F1GACTU" 0805_HV 1715,7735 r90 bottom value=0.01uF
C265 "C0805C104K1RACTU" 0805_HV 1824.09,8098.58 r180 bottom value=0.1uF
C266 "C0805C103F1GACTU" 0805_HV 1824.09,8018.58 r180 bottom value=0.01uF
C267 "12065C104JAT2A" 1206 2525,4270 r90 bottom value=0.1uF
C268 "12065C104JAT2A" 1206 2525,4270 r90 top value=0.1uF
C269 "KTS250B336M55N0T00" 2220_310 2350,4270 r270 top value=33uF
C270 "22201C106MAT2A" 2220_280 2350,4270 r270 bottom value=10uF
C271 "Capacitor" 0805_HV 1535,4340 r0 top value=0.01uF
C272 "Cap_Polarized" 7343-43 635,4085 r270 top value=10uF
C273 "CMP-0011955-2" 7343-43 635,4085 r270 bottom value=220uF
C274 "CMP-0011955-2" 7343-43 1820,4045 r270 top value=220uF
C275 "C0805C104K3RACTU" 0805_HV 780,4085 r270 top value=0.1uF
C276 "CMP-0008376-2" 0805_HV 780,4085 r270 bottom value=0.01uF
C277 "C0805C104K3RACTU" 0805_HV 1515,4085 r270 top value=0.1uF
C278 "CGA8M2X7R1H335K200KA" 1812_220 1640,4085 r270 top value=3.3uF
C279 "CGA8M2X7R1H335K200KA" 1812_220 1640,4085 r270 bottom value=3.3uF
C280 "12065C104JAT2A" 1206 2525,3845 r90 bottom value=0.1uF
C281 "12065C104JAT2A" 1206 2525,3845 r90 top value=0.1uF
C282 "KTS250B336M55N0T00" 2220_310 2350,3843.03 r270 top value=33uF
C283 "22201C106MAT2A" 2220_280 2350,3845 r270 bottom value=10uF
C284 "Capacitor" 0805_HV 950,4475 r0 top value=2000pF
C285 "Capacitor" 1206_180 1345,4475 r180 top value=0.1uF
C286 "12065C104JAT2A" 1206 2525,6125.79 r90 bottom value=0.1uF
C287 "12065C104JAT2A" 1206 2525,6125.79 r90 top value=0.1uF
C288 "KTS250B336M55N0T00" 2220_310 2350,6125.79 r270 top value=33uF
C289 "22201C106MAT2A" 2220_280 2350,6125.79 r270 bottom value=10uF
C290 "Capacitor" 0805_HV 1535,6194.53 r0 top value=0.01uF
C291 "Cap_Polarized" 7343-43 635,5939.53 r270 top value=10uF
C292 "CMP-0011955-2" 7343-43 635,5939.53 r270 bottom value=220uF
C293 "CMP-0011955-2" 7343-43 1820,5899.53 r270 top value=220uF
C294 "C0805C104K3RACTU" 0805_HV 780,5939.53 r270 bottom value=0.1uF
C295 "Capacitor" 0805_HV 780,5939.53 r270 top value=0.01uF
C296 "C0805C104K3RACTU" 0805_HV 1515,5940 r270 top value=0.1uF
C297 "CGA8M2X7R1H335K200KA" 1812_220 1640,5939.53 r270 top value=3.3uF
C298 "CGA8M2X7R1H335K200KA" 1812_220 1640,5939.53 r270 bottom value=3.3uF
C299 "12065C104JAT2A" 1206 2525,5700.79 r90 bottom value=0.1uF
C300 "12065C104JAT2A" 1206 2525,5700.79 r90 top value=0.1uF
C301 "KTS250B336M55N0T00" 2220_310 2350,5700.79 r270 top value=33uF
C302 "22201C106MAT2A" 2220_280 2350,5700.79 r270 bottom value=10uF
C303 "CMP-0008070-2" 0805_HV 950,6329.53 r0 top value=2000pF
C304 "CMP-0064950-2" 1206_180 1345,6329.53 r180 top value=0.1uF
C305 "12065C104JAT2A" 1206 2525,5185 r90 bottom value=0.1uF
C306 "12065C104JAT2A" 1206 2525,5185 r90 top value=0.1uF
C307 "KTS250B336M55N0T00" 2220_310 2350,5180 r270 top value=33uF
C308 "22201C106MAT2A" 2220_280 2350,5180 r270 bottom value=10uF
C309 "Capacitor" 0805_HV 1535,5290 r0 top value=0.01uF
C310 "Cap_Polarized" 7343-43 635,5035 r270 top value=10uF
C311 "CMP-0011955-2" 7343-43 635,5035 r270 bottom value=220uF
C312 "CMP-0011955-2" 7343-43 1820,4995 r270 top value=220uF
C313 "C0805C104K3RACTU" 0805_HV 780,5035 r270 bottom value=0.1uF
C314 "Capacitor" 0805_HV 780,5035 r270 top value=0.01uF
C315 "C0805C104K3RACTU" 0805_HV 1515,5035 r270 top value=0.1uF
C316 "CMP-0006210-2" 0402_065 1866,780 r90 top value=0.01uF
C317 "CMP-0006210-2" 0402_065 1911,780 r90 top value=0.01uF
C318 "CMP-0006210-2" 0402_065 1810,1845 r270 top value=0.01uF
C319 "CMP-0006210-2" 0402_065 1855,1845 r270 top value=0.01uF
C320 "CMP-0006210-2" 0402_065 2375,1570 r180 top value=0.01uF
C321 "CMP-0006210-2" 0402_065 2375,1525 r180 top value=0.01uF
C322 "CMP-0006210-2" 0402_065 2375,1355 r180 top value=0.01uF
C323 "CMP-0006210-2" 0402_065 2375,1310 r180 top value=0.01uF
C324 "CMP-0006210-2" 0402_065 2375,1095 r180 top value=0.01uF
C325 "CMP-0006210-2" 0402_065 2375,1140 r180 top value=0.01uF
C326 "CGA8M2X7R1H335K200KA" 1812_220 1640,5035 r270 top value=3.3uF
C327 "Capacitor" 0603 1805,3240 r270 bottom value=0.1uF
C328 "Capacitor" 0603 1685,3240 r270 bottom value=0.1uF
C329 "Capacitor" 0603 1745,3240 r270 bottom value=0.1uF
C331 "GRM155R6YA105KE11D" 0402 9541.66,2640.49 r180 top value=1uF
C332 "GRM155R6YA105KE11D" 0402 9502.44,6288.09 r180 top value=1uF
C333 "GRM155R6YA105KE11D" 0402 9542.59,3140.15 r180 top value=1uF
C334 "CGA8M2X7R1H335K200KA" 1812_220 1640,5035 r270 bottom value=3.3uF
C335 "Capacitor" 0603 1865,3240 r270 bottom value=0.01uF
C337 "Capacitor" 0805_HV 1940,3240 r270 bottom value=1000pF
C339 "12065C104JAT2A" 1206 2525,4755 r90 bottom value=0.1uF
C340 "12065C104JAT2A" 1206 2525,4755 r90 top value=0.1uF
C341 "KTS250B336M55N0T00" 2220_310 2350,4755 r270 top value=33uF
C342 "22201C106MAT2A" 2220_280 2350,4755 r270 bottom value=10uF
C343 "Capacitor" 0805_HV 950,5425 r0 top value=2000pF
C344 "Capacitor" 1206_180 1345,5425 r180 top value=0.1uF
C345 "TPSC336K010R0375" 6032-28 1045,6847.56 r270 top value=33uF
C346 "TPSD226K025R0100" 7343-31 620,6992.56 r90 top value=22uF
C347 "CGJ4C2C0G1H471J060AA" 0805_HV 1360,6837.56 r90 top value=470pF
C348 "C0805C104K3RACTU" 0805_HV 1490,7142.56 r0 top value=0.1uF
C349 "22201C106MAT2A" 2220_280 845,6992.56 r90 top value=10uF
C350 "CGA8M2X7R1H335K200KA" 1812_220 1105,7127.56 r90 top value=3.3uF
C351 "TPSD156K035R0300" 7343-31 2415,6931.65 r90 bottom value=15uF
C352 "CMP-0011955-2" 7343-43 2155,6917.56 r90 bottom value=220uF
C353 "C4532X7R2A105K230KA" 1812_254 2415,6937.56 r90 top value=1uF
C354 "22201C106MAT2A" 2220_280 2155,6927.56 r90 top value=10uF
C355 "GRM155R71E103KA01D" 0402 4878.03,5060 r0 bottom value=0.01uF
C356 "GRM155R71E103KA01D" 0402 4675,4985 r270 bottom value=0.01uF
CE_TP1 "5007" Keystone5007 7975,1565 r0 top
CE_TP2 "5007" Keystone5007 6230,8305 r180 top
CE_TP3 "5007" Keystone5007 8305.5,5282.55 r90 top
D1 "LED" LTST-C191_Green 4066.89,4412 r0 top value=Green
D2 "LED" LTST-C191_Green 4066.89,4328.46 r0 top value=Green
D3 "LED" LTST-C191_Green 4066.89,4583.46 r0 top value=Green
D4 "LED" LTST-C191_Green 4066.89,4498.46 r0 top value=Green
D5 "CMP-0002891-3" LTST-C191_Green 7272.76,755.63 r225 top value=Green
D6 "CMP-0002891-3" LTST-C191_Green 6959.59,9087.35 r45 top value=Green
D7 "LTST-C191KGKT" LTST-C191_Green 2790,2837.44 r0 top value=Green
D10 "LED" LTST-C191_Green 1520,2825.59 r270 top value=Green
D12 "B320B-13-F" SMB 1170,7870 r0 top value=20V
D13 "CMP-0002891-3" LTST-C191_Green 9087.85,4552.96 r315 top value=Green
D14 "LTST-C191KGKT" LTST-C191_Green 3782.19,100 r270 top value=Green
D15 "LTST-C191KGKT" LTST-C191_Green 3887.19,100 r270 top value=Green
D16 "LTST-C191KGKT" LTST-C191_Green 3992.19,100 r270 top value=Green
D17 "LTST-C191KGKT" LTST-C191_Green 4097.19,100 r270 top value=Green
D18 "LTST-C191KGKT" LTST-C191_Green 4202.19,100 r270 top value=Green
D19 "LTST-C191KGKT" LTST-C191_Green 4307.19,100.12 r270 top value=Green
D20 "LTST-C191KGKT" LTST-C191_Green 4411.28,100.12 r270 top value=Green
D21 "1N6642UD1" ST_LCC-2D 1180,6837.56 r90 bottom value=100V
D22 "1N6642UD1" ST_LCC-2D 930,6790 r0 bottom value=100V
FID1 "Fiducial" Fiducial10-20 9100,800 r0 top
FID2 "Fiducial" Fiducial10-20 9100,9000 r0 top
FID3 "Fiducial" Fiducial10-20 400,3580 r0 top
FID4 "Fiducial" Fiducial10-20 9100,620 r180 bottom
FID5 "Fiducial" Fiducial10-20 9100,8820 r180 bottom
FID6 "Fiducial" Fiducial10-20 400,3400 r180 bottom
J1 "SMA_Contact1_GND2345" Johnson_142-0701-20x 4843,3850 r45 top
J2 "SMA_Contact1_GND2345" Johnson_142-0701-20x 4070,5173 r0 top
J3 "SMA_Contact1_GND2345" Johnson_142-0701-20x 4070,4797 r0 top
J4 "SMA_Contact1_GND2345" Johnson_142-0701-20x 5340,3850 r315 top
J5 "SMA_Contact1_GND2345" Johnson_142-0701-20x 6968.23,5871.77 r315 top
J6 "SMA_Contact1_GND2345" Johnson_142-0701-20x 8260,6280 r0 top
J7 "142-0771-831" Johnson_142-0771-831 2683,1 r180 top
J8 "HTSW-102-07-G-S" Samtec_HTSW-102-07-G-S 625,1905 r90 top
J9 "142-0771-831" Johnson_142-0771-831 2083,1 r180 top
J10 "SMA_Contact1_GND2345" Johnson_142-0701-20x 8260,6780 r90 top
J11 "142-0771-831" Johnson_142-0771-831 9841.56,6787.89 r270 top
J12 "HTSW-102-07-G-S" Samtec_HTSW-102-07-G-S 7603.25,6859.9 r180 top
J13 "SMA_Contact1_GND2345" Johnson_142-0701-20x 5125,6195 r45 top
J14 "SMA_Contact1_GND2345" Johnson_142-0701-20x 7845,7150 r315 top
J15 "SMA_Contact1_GND2345" Johnson_142-0701-20x 5625,6195 r45 top
J16 "HTSW-102-07-G-S" Samtec_HTSW-102-07-G-S 440,1055 r0 top
J17 "678038020" FP-678038020_CONN_USB-MFG 185,2835 r0 top
J18 "SMA_Contact1_GND2345" Johnson_142-0701-20x 7845,5915 r315 top
J19 "CMP-0055434-2" FCI_52601-S10-8LF 1245,3532.56 r270 top
J20 "TSW-110-07-G-D" TSW-110-07-G-D 2130,2995 r270 top
J21 "142-0701-201" Johnson_142-0701-20x 8082.82,591.31 r45 top
J22 "142-0701-201" Johnson_142-0701-20x 8092.82,1816.31 r45 top
J24 "142-0701-201" Johnson_142-0701-20x 6154.91,9257.44 r45 top
J25 "142-0771-831" Johnson_142-0771-831 1482.61,0 r180 top
J26 "142-0701-201" Johnson_142-0701-20x 6154.91,8032.44 r135 top
J27 "142-0771-831" Johnson_142-0771-831 883,0 r180 top
J30 "HTSW-103-07-G-S" Samtec_HTSW-103-07-G-S 1456,1725 r0 top
J32 "CMP-0075524-1" Samtec_QSH-030-01-X-D-A 5099.13,749.32 r270 top
J33 "CMP-0075524-1" Samtec_QSH-030-01-X-D-A 5076.61,9385.68 r90 top
J37 "142-0701-201" Johnson_142-0701-20x 9247.27,5358.11 r135 top
J38 "142-0701-201" Johnson_142-0701-20x 8045.58,5354.94 r225 top
J39 "HTSW-102-07-G-S" Samtec_HTSW-102-07-G-S 1620,2610.59 r270 top
J40 "HTSW-102-07-G-S" Samtec_HTSW-102-07-G-S 9155,6190 r0 top
J41 "SMA_Contact1_GND2345" Johnson_142-0701-20x 9110,5935 r270 top
J42 "SMA_Contact1_GND2345" Johnson_142-0701-20x 9063.94,7105 r0 top
J43 "HTSW-102-07-G-S" Samtec_HTSW-102-07-G-S 2987.56,8725 r270 top
J44 "RAPC722X" CONN_RAPC722X 2670,9840 r90 top
J45 "HTSW-103-07-G-S" Samtec_HTSW-103-07-G-S 2170,9670 r0 top
J46 "HTSW-102-07-G-S" Samtec_HTSW-102-07-G-S 1577.56,8725 r270 top
J47 "RAPC722X" CONN_RAPC722X 1265,9840 r90 top
J48 "HTSW-103-07-G-S" Samtec_HTSW-103-07-G-S 755,9670 r0 top
J49 "HTSW-102-07-G-S" Samtec_HTSW-102-07-G-S 1675,4460 r270 top
J50 "HTSW-102-07-G-S" Samtec_HTSW-102-07-G-S 695,4400 r270 top
J51 "HTSW-102-07-G-S" Samtec_HTSW-102-07-G-S 1675,6314.53 r270 top
J52 "HTSW-102-07-G-S" Samtec_HTSW-102-07-G-S 695,6254.53 r270 top
J53 "HTSW-102-07-G-S" Samtec_HTSW-102-07-G-S 1675,5410 r270 top
J54 "HTSW-102-07-G-S" Samtec_HTSW-102-07-G-S 695,5350 r270 top
J55 "142-0771-831" Johnson_142-0771-831 9849.59,2640.52 r270 top
J56 "HTSW-103-07-G-S" Samtec_HTSW-103-07-G-S 2005,6687.56 r0 top
J57 "142-0771-831" Johnson_142-0771-831 9841.56,6287.89 r270 top
J58 "142-0771-831" Johnson_142-0771-831 9849.59,3140.52 r270 top
J59 "HTSW-102-07-G-S" Samtec_HTSW-102-07-G-S 1310,6692.56 r180 top
L1 "Ferrite_Bead" 0603 4805,4994 r180 bottom value="120 ohm"
L2 "Ferrite_Bead" 0603 5350.93,4940.18 r270 bottom value="120 ohm"
L3 "Ferrite_Bead" 0603 4805,4935 r180 bottom value="120 ohm"
L4 "Ferrite_Bead" 0603 5194.17,5225 r90 bottom value="120 ohm"
L5 "Ferrite_Bead" 0603 4540.61,4727.52 r180 top value="120 ohm"
L6 "Ferrite_Bead" 0603 4820.74,4757.5 r270 bottom value="120 ohm"
L7 "Ferrite_Bead" 0603 5105,5225 r90 bottom value="120 ohm"
L8 "Ferrite_Bead" 0603 5025,5225 r90 bottom value="120 ohm"
L9 "Ferrite_Bead" 0603 4958.62,4648.5 r270 bottom value="120 ohm"
L10 "Ferrite_Bead" 0603 5165,4620 r270 bottom value="120 ohm"
L11 "CMP-0058614-1" IND_LQG15H 7616.1,823.97 r270 bottom value=18nH
L12 "CMP-0058614-1" IND_LQG15H 7310.2,1116.31 r180 bottom value=18nH
L13 "Ferrite_Bead" 0603 575,1765 r0 top value="120 ohm"
L14 "Inductor_Iron" IND_LQG15H 9519.07,2708.7 r270 top value=1nH
L15 "Ferrite_Bead" 1206 975,2990 r180 bottom value="120 ohm"
L16 "Ferrite_Bead" 1206 820,2555.59 r180 top value="120 ohm"
L17 "CIM10U800NC" 0603 1305,1946.3 r0 top value="80 ohm"
L18 "CMP-0058614-1" IND_LQG15H 6615,9025 r90 bottom value=18nH
L19 "CMP-0058614-1" IND_LQG15H 6934.26,8727.4 r0 bottom value=18nH
L21 "CMP-0058614-1" IND_LQG15H 9025.5,4897.55 r0 bottom value=18nH
L22 "CMP-0058614-1" IND_LQG15H 8731,4600 r270 bottom value=18nH
L23 "AE611PYA222MSZ" AE611PYA_1011 790,7760 r180 top value=2.2uH
L24 "Ferrite_Bead" 1206 2200,4475 r0 top value="120 ohm"
L25 "Ferrite_Bead" 1206 2200,4050 r0 top value="120 ohm"
L26 "Ferrite_Bead" 1206 2200,6330.79 r0 top value="120 ohm"
L27 "Ferrite_Bead" 1206 2200,5905.79 r0 top value="120 ohm"
L28 "Ferrite_Bead" 1206 2200,5385 r0 top value="120 ohm"
L29 "Ferrite_Bead" 1206 2200,4960 r0 top value="120 ohm"
L30 "Ferrite_Bead" 0603 4800,5095 r90 bottom value="120 ohm"
L31 "Ferrite_Bead" 0603 4585,5010 r180 bottom value="120 ohm"
L32 "Inductor_Iron" IND_LQG15H 9426,6307 r270 top value=1nH
L37 "Inductor_Iron" IND_LQG15H 9502.44,6333.09 r0 top value=1nH
L38 "Inductor_Iron" IND_LQG15H 9546.17,3185 r0 top value=1nH
L39 "Inductor_Iron" IND_LQG15H 9504.79,6742.98 r0 top value=1nH
L40 "Inductor_Iron" IND_LQG15H 9546.17,2596.05 r0 top value=1nH
LBL1 "Label" Label_650x200 5075,2075 r0 top
Logo1 "Pb-Free Symbol" Pb-Free_Overlay_Small 5075,2325 r0 top
Logo2 "FCC disclaimer" FCC_disclaimer 5050,1820 r0 top
Logo3 "WEEE logo" WEEE_Minimum 5600,2075 r0 top
Logo4 "ESD Susceptible" ESD_Overlay_Small 4550,2075 r0 top
NT1 "Net-Tie" Net-Tie_0805_HV_NoOverlay 1579,3271 r180 top net-tie
NT2 "Net-Tie" Net-Tie_0805_HV_NoOverlay 930,3585 r270 bottom net-tie
OSCinM1 "142-0701-201" Johnson_142-0701-20x 7354.35,2359.11 r270 top
OSCinM2 "142-0701-201" Johnson_142-0701-20x 6878,7483.87 r90 top
OSCinM3 "CMP-0055819-1" Johnson_142-0701-20x 7484.37,4634.55 r0 top
OSCinN "SMA_Contact1_GND2345" Emerson_142-0701-851 5.09,1183.92 r90 top locked
OSCinP "SMA_Contact1_GND2345" Emerson_142-0701-851 5.09,1674.12 r90 top locked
